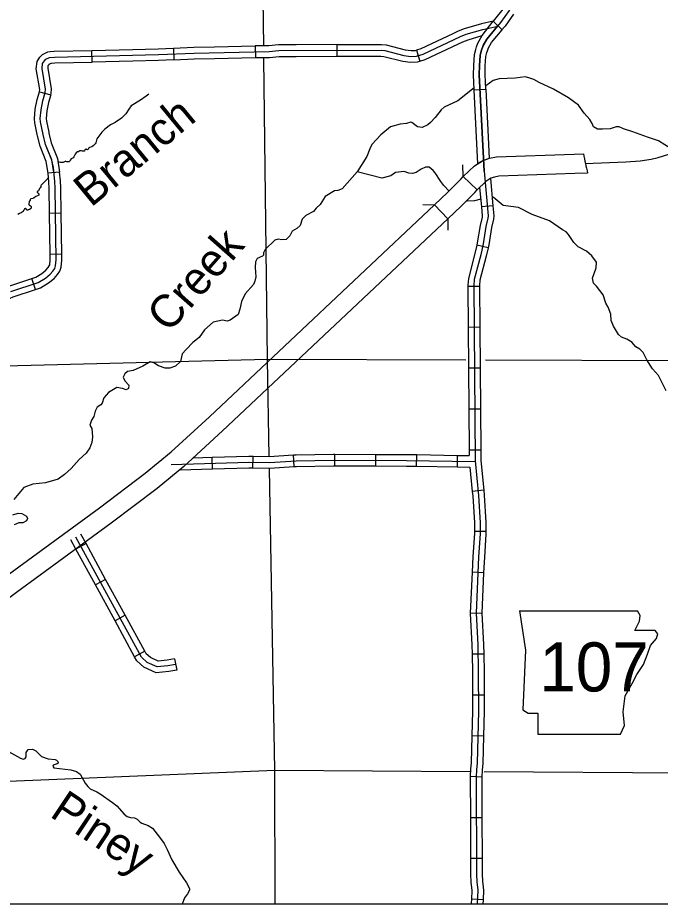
# Model space of a CAD drawing. Extents: x 1212896 to 1368412, y 378476 to 478763.
# Drawn here: x 1265961 to 1274256, y 388319 to 399763 of the extents above; entities that cross this region are included whole.
import ezdxf

# ---------------------------------------------------------------- set-up
doc = ezdxf.new("R2010")
doc.units = 0
for name, color, linetype in [('1', 7, 'Continuous'), ('Level 10', 7, 'Continuous'), ('Level 21', 7, 'Continuous'), ('Level 31', 7, 'Continuous'), ('Level 32', 7, 'Continuous'), ('Level 35', 7, 'Continuous'), ('Level 37', 7, 'Continuous'), ('Level 5', 7, 'Continuous'), ('Level 60', 7, 'Continuous')]:
    doc.layers.add(name, color=color, linetype=linetype)

msp = doc.modelspace()

# ---------------------------------------------------------------- linework, layer by layer
at = {"layer": '1'}
msp.add_lwpolyline([(1257400, 437504), (1319317, 437504), (1319317, 388319), (1257400, 388319)], close=True, dxfattribs=at)
at = {"layer": 'Level 10'}
for p, q in [((1271893, 397542), (1271710, 397712)), ((1271342, 397349), (1271515, 397169))]:
    msp.add_line(p, q, dxfattribs=at)
for points in [[(1273285, 397881), (1273811, 397904), (1273995, 397914), (1274137, 397939), (1274230, 397960), (1274366, 398002), (1274402, 398020), (1274547, 398112), (1275239, 398349)], [(1271710, 397712), (1271856, 397852), (1271961, 397917), (1272051, 397948), (1272143, 397966), (1273145, 398000), (1273262, 398005)], [(1271342, 397349), (1271511, 397509), (1271682, 397681), (1271710, 397712)], [(1273317, 397758), (1273154, 397751), (1272172, 397717), (1272116, 397706), (1272069, 397690), (1272004, 397650), (1271893, 397542)], [(1271515, 397169), (1271685, 397330), (1271863, 397509), (1271893, 397542)], [(1264197, 391366), (1264233, 391409), (1264355, 391513), (1265223, 392114), (1265798, 392545), (1267017, 393438), (1267605, 393882), (1267944, 394160), (1268436, 394612), (1271342, 397349)], [(1271515, 397169), (1268606, 394429), (1268107, 393971), (1267759, 393686), (1267166, 393238), (1265947, 392344), (1265369, 391912), (1264508, 391315), (1264410, 391231), (1264386, 391203)]]:
    msp.add_lwpolyline(points, dxfattribs=at)
msp.add_arc((1280772, 399533), 7663, 191.4984, 193.3964, dxfattribs=at)
at = {"layer": 'Level 21'}
for p, q in [((1272439, 392107), (1272516, 391600)), ((1273996, 392048), (1273961, 392107)), ((1273928, 391854), (1273987, 391972)), ((1273987, 391972), (1273996, 392048)), ((1274190, 391854), (1273928, 391854)), ((1274224, 391811), (1274190, 391854)), ((1274131, 391659), (1274207, 391752)), ((1274207, 391752), (1274224, 391811)), ((1272516, 391600), (1272482, 390830)), ((1274089, 391549), (1274131, 391659)), ((1274038, 391414), (1274089, 391549)), ((1273954, 391287), (1274038, 391414)), ((1273894, 391168), (1273954, 391287)), ((1273801, 391008), (1273894, 391168)), ((1273776, 390805), (1273801, 391008)), ((1272482, 390830), (1272549, 390788)), ((1273793, 390627), (1273776, 390805)), ((1272549, 390788), (1272676, 390788)), ((1272676, 390788), (1272676, 390517)), ((1273742, 390517), (1273793, 390627)), ((1272676, 390517), (1273742, 390517))]:
    msp.add_line(p, q, dxfattribs=at)
msp.add_lwpolyline([(1272439, 392107), (1273961, 392107)], dxfattribs=at)
at = {"layer": 'Level 31'}
for p, q in [((1269028, 399398), (1269031, 399248)), ((1270085, 399266), (1270085, 399416)), ((1266920, 399191), (1266917, 399341)), ((1267971, 399370), (1267977, 399220)), ((1271109, 399345), (1271153, 399202)), ((1271854, 398833), (1272004, 398841)), ((1266242, 398808), (1266387, 398768)), ((1266502, 397771), (1266353, 397756))]:
    msp.add_line(p, q, dxfattribs=at)
for points in [[(1266428, 397764), (1266400, 397927), (1266321, 398126), (1266290, 398256), (1266257, 398418), (1266252, 398460), (1266262, 398573), (1266287, 398688), (1266317, 398797), (1266320, 398840), (1266276, 399107), (1266282, 399171), (1266307, 399208), (1266324, 399226), (1266370, 399248), (1266436, 399255), (1267777, 399287), (1268237, 399306), (1269209, 399326), (1269330, 399338), (1270652, 399343), (1270702, 399338), (1270946, 399276), (1271037, 399263), (1271109, 399267), (1271194, 399293), (1271676, 399519), (1271749, 399550), (1271965, 399613), (1272160, 399656)], [(1272099, 399719), (1271947, 399686), (1271724, 399621), (1271645, 399588), (1271580, 399557)], [(1271981, 397782), (1271920, 399027), (1271922, 399145), (1271932, 399276), (1271945, 399333), (1271970, 399405), (1272016, 399484), (1272156, 399655)], [(1271958, 399533), (1272099, 399719)], [(1272099, 399719), (1272214, 399607)], [(1271580, 399557), (1271167, 399363), (1271109, 399345)], [(1271644, 399422), (1271706, 399451), (1271774, 399479), (1271958, 399533)], [(1271884, 399386), (1271902, 399436), (1271958, 399533)], [(1272026, 399336), (1272039, 399373), (1272078, 399441), (1272214, 399607)], [(1267971, 399370), (1268235, 399381), (1268500, 399387)], [(1268500, 399387), (1269028, 399398)], [(1269557, 399414), (1269326, 399413), (1269204, 399401), (1269028, 399398)], [(1270085, 399416), (1269557, 399414)], [(1270085, 399416), (1270613, 399418)], [(1270613, 399418), (1270656, 399418), (1270716, 399412), (1270961, 399350), (1271040, 399339), (1271096, 399341), (1271109, 399345)], [(1271153, 399202), (1271221, 399222), (1271644, 399422)], [(1271854, 398833), (1271845, 399026), (1271847, 399148), (1271857, 399287), (1271873, 399354), (1271884, 399386)], [(1266242, 398808), (1266243, 398811), (1266245, 398837), (1266201, 399105), (1266210, 399196), (1266248, 399255), (1266280, 399288), (1266350, 399321), (1266382, 399325)], [(1266382, 399325), (1266430, 399330), (1266917, 399341)], [(1266917, 399341), (1267445, 399354)], [(1267445, 399354), (1267775, 399362), (1267971, 399370)], [(1270085, 399266), (1270613, 399268)], [(1270613, 399268), (1270648, 399268), (1270689, 399264), (1270932, 399202), (1271033, 399188), (1271122, 399192), (1271153, 399202)], [(1272004, 398841), (1271995, 399028), (1271997, 399141), (1272006, 399264), (1272017, 399312), (1272026, 399336)], [(1266387, 398768), (1266391, 398784), (1266396, 398844), (1266352, 399110), (1266355, 399145), (1266365, 399160), (1266368, 399164), (1266391, 399175), (1266399, 399176)], [(1266399, 399176), (1266441, 399180), (1266920, 399191)], [(1267448, 399204), (1266920, 399191)], [(1267977, 399220), (1267780, 399212), (1267448, 399204)], [(1267977, 399220), (1268240, 399231), (1268503, 399237)], [(1268503, 399237), (1269031, 399248)], [(1269031, 399248), (1269213, 399251), (1269334, 399263), (1269557, 399264)], [(1269557, 399264), (1270085, 399266)], [(1271880, 398306), (1271854, 398833)], [(1272004, 398841), (1272030, 398313)], [(1266214, 398255), (1266183, 398406), (1266177, 398459), (1266188, 398584), (1266214, 398706), (1266242, 398808)], [(1266387, 398768), (1266360, 398670), (1266336, 398562), (1266328, 398460), (1266331, 398429), (1266361, 398286)], [(1266353, 397756), (1266327, 397907), (1266250, 398104), (1266217, 398240), (1266214, 398255)], [(1266361, 398286), (1266363, 398273), (1266393, 398149), (1266473, 397947), (1266502, 397771)], [(1271901, 397880), (1271880, 398306)], [(1272030, 398313), (1272048, 397947)], [(1272048, 397947), (1271961, 397917), (1271901, 397880)]]:
    msp.add_lwpolyline(points, dxfattribs=at)
at = {"layer": 'Level 32'}
for p, q in [((1272096, 397336), (1271947, 397322)), ((1266523, 397238), (1266373, 397236)), ((1272034, 396793), (1271887, 396825)), ((1266529, 396710), (1266379, 396708)), ((1266192, 396255), (1266145, 396398)), ((1271923, 396295), (1271773, 396294)), ((1271927, 395767), (1271777, 395766)), ((1271931, 395239), (1271781, 395238)), ((1271935, 394711), (1271785, 394710)), ((1269531, 393970), (1269522, 394119)), ((1270054, 393980), (1270055, 394130)), ((1270582, 393977), (1270583, 394127)), ((1271109, 393973), (1271112, 394123)), ((1271939, 394183), (1271789, 394182)), ((1268474, 393941), (1268469, 394090)), ((1268998, 393954), (1269001, 394104)), ((1271637, 393964), (1271640, 394114)), ((1271978, 393663), (1271829, 393649)), ((1272006, 393129), (1271856, 393129)), ((1266843, 392976), (1266711, 392904)), ((1271975, 392599), (1271826, 392606)), ((1267096, 392513), (1266964, 392441)), ((1271951, 392079), (1271801, 392071)), ((1267349, 392049), (1267217, 391978)), ((1267602, 391586), (1267470, 391514)), ((1267983, 391489), (1268013, 391342)), ((1271976, 391549), (1271826, 391546)), ((1271982, 391020), (1271832, 391019)), ((1271975, 390490), (1271825, 390493)), ((1271953, 389962), (1271803, 389967)), ((1271954, 389437), (1271804, 389436)), ((1271956, 388909), (1271806, 388908)), ((1271968, 388378), (1271818, 388385))]:
    msp.add_line(p, q, dxfattribs=at)
for points in [[(1272636, 400916), (1272539, 400477), (1272461, 400213), (1272421, 400100), (1272345, 399927), (1272306, 399857), (1272194, 399700), (1272016, 399484), (1271970, 399405), (1271945, 399333), (1271932, 399276), (1271922, 399145), (1271920, 399027), (1271981, 397782)], [(1272239, 399894), (1272099, 399719)], [(1272360, 399807), (1272252, 399655), (1272203, 399596)], [(1265874, 396228), (1266226, 396344), (1266318, 396399), (1266379, 396451), (1266416, 396492), (1266438, 396525), (1266450, 396559), (1266456, 396636), (1266445, 397562), (1266440, 397651), (1266422, 397830), (1266400, 397926), (1266321, 398126), (1266290, 398256), (1266257, 398418), (1266252, 398460), (1266262, 398573), (1266287, 398688), (1266317, 398797), (1266320, 398840), (1266276, 399107), (1266282, 399171), (1266307, 399208), (1266324, 399226), (1266370, 399248), (1266436, 399255), (1267777, 399287), (1268237, 399306), (1269209, 399326), (1269330, 399338), (1270652, 399343), (1270702, 399338), (1270946, 399276), (1271037, 399263), (1271109, 399267), (1271194, 399293), (1271676, 399519), (1271749, 399550), (1271965, 399613), (1272160, 399656)], [(1271981, 397782), (1272034, 397207), (1272031, 397176), (1272006, 397068), (1271969, 396844), (1271938, 396703), (1271855, 396386), (1271849, 396307), (1271867, 394042), (1271911, 393596), (1271932, 393243), (1271932, 393101), (1271911, 392803), (1271878, 392077), (1271899, 391670), (1271907, 391314), (1271909, 390813), (1271893, 390141), (1271882, 390061), (1271879, 389956), (1271883, 388708), (1271887, 388611), (1271900, 388500), (1271892, 388325), (1271891, 388319)], [(1266373, 397236), (1266369, 397559), (1266364, 397645), (1266353, 397756)], [(1266523, 397238), (1266519, 397565), (1266514, 397656), (1266502, 397771)], [(1272063, 397688), (1272096, 397336)], [(1271924, 397571), (1271947, 397322)], [(1271947, 397322), (1271957, 397207), (1271955, 397188), (1271931, 397083), (1271894, 396858), (1271887, 396825)], [(1272096, 397336), (1272108, 397207), (1272104, 397164), (1272078, 397054), (1272042, 396830), (1272034, 396793)], [(1266379, 396708), (1266373, 397236)], [(1266529, 396710), (1266523, 397238)], [(1271887, 396825), (1271864, 396721), (1271779, 396398), (1271773, 396310), (1271773, 396294)], [(1272034, 396793), (1272010, 396686), (1271928, 396374), (1271923, 396305), (1271923, 396295)], [(1266145, 396398), (1266194, 396414), (1266273, 396462), (1266326, 396506), (1266355, 396538), (1266369, 396559), (1266374, 396575), (1266380, 396639), (1266379, 396708)], [(1266192, 396255), (1266257, 396277), (1266360, 396339), (1266431, 396398), (1266475, 396447), (1266505, 396492), (1266522, 396543), (1266530, 396633), (1266529, 396710)], [(1265645, 396210), (1265847, 396299), (1266145, 396398)], [(1271773, 396294), (1271777, 395766)], [(1271923, 396295), (1271927, 395767)], [(1265705, 396073), (1265901, 396159), (1266192, 396255)], [(1271777, 395766), (1271781, 395238)], [(1271927, 395767), (1271931, 395239)], [(1271781, 395238), (1271785, 394710)], [(1271931, 395239), (1271935, 394711)], [(1271785, 394710), (1271789, 394182)], [(1271935, 394711), (1271939, 394183)], [(1269001, 394104), (1269209, 394100), (1269522, 394119)], [(1269522, 394119), (1269554, 394121), (1270038, 394130), (1270055, 394130)], [(1270055, 394130), (1270583, 394127)], [(1270583, 394127), (1270979, 394126), (1271112, 394123)], [(1271112, 394123), (1271640, 394114)], [(1271789, 394182), (1271790, 394112)], [(1271939, 394183), (1271940, 394046), (1271978, 393663)], [(1267944, 393998), (1268945, 394028), (1269211, 394023), (1269557, 394045), (1270039, 394053), (1270978, 394049), (1271867, 394034)], [(1268230, 394083), (1268469, 394090)], [(1268469, 394090), (1268944, 394105), (1269001, 394104)], [(1271640, 394114), (1271790, 394112)], [(1268055, 393928), (1268474, 393941)], [(1268474, 393941), (1268945, 393955), (1268998, 393954)], [(1268998, 393954), (1269212, 393950), (1269531, 393970)], [(1269531, 393970), (1269560, 393971), (1270039, 393980), (1270054, 393980)], [(1270054, 393980), (1270582, 393977)], [(1270582, 393977), (1270978, 393976), (1271109, 393973)], [(1271109, 393973), (1271637, 393964)], [(1271637, 393964), (1271798, 393962)], [(1271798, 393962), (1271829, 393649)], [(1271978, 393663), (1271984, 393602), (1272006, 393246), (1272006, 393129)], [(1271829, 393649), (1271834, 393590), (1271856, 393241), (1271856, 393129)], [(1266843, 392976), (1266777, 393096)], [(1271856, 393129), (1271856, 393104), (1271835, 392807), (1271826, 392606)], [(1272006, 393129), (1272006, 393098), (1271985, 392798), (1271975, 392599)], [(1266711, 392904), (1266646, 393024)], [(1267998, 391415), (1267900, 391396), (1267762, 391383), (1267631, 391442), (1267559, 391507), (1266712, 393060)], [(1267096, 392513), (1266843, 392976)], [(1266964, 392441), (1266711, 392904)], [(1271826, 392606), (1271801, 392077), (1271801, 392071)], [(1271975, 392599), (1271951, 392078)], [(1267217, 391978), (1266964, 392441)], [(1267349, 392049), (1267096, 392513)], [(1271801, 392071), (1271823, 391668), (1271826, 391546)], [(1271951, 392079), (1271973, 391673), (1271976, 391549)], [(1267470, 391514), (1267217, 391978)], [(1267602, 391586), (1267349, 392049)], [(1268013, 391342), (1267911, 391322), (1267750, 391306), (1267590, 391378), (1267500, 391460), (1267470, 391514)], [(1267983, 391489), (1267889, 391470), (1267775, 391459), (1267673, 391505), (1267619, 391554), (1267602, 391586)], [(1271826, 391546), (1271831, 391313), (1271832, 391019)], [(1271976, 391549), (1271981, 391315), (1271982, 391020)], [(1271832, 391019), (1271833, 390814), (1271825, 390493)], [(1271982, 391020), (1271983, 390813), (1271975, 390490)], [(1271825, 390493), (1271816, 390146), (1271806, 390067), (1271803, 389967)], [(1271975, 390490), (1271966, 390135), (1271956, 390055), (1271953, 389962)], [(1271803, 389967), (1271802, 389957), (1271804, 389436)], [(1271953, 389962), (1271952, 389955), (1271954, 389437)], [(1271804, 389436), (1271806, 388908)], [(1271954, 389437), (1271956, 388909)], [(1271806, 388908), (1271807, 388706), (1271811, 388605), (1271823, 388497), (1271818, 388385)], [(1271956, 388909), (1271957, 388709), (1271960, 388616), (1271973, 388503), (1271968, 388378)], [(1271818, 388385), (1271815, 388332), (1271814, 388319)], [(1271968, 388378), (1271965, 388319)]]:
    msp.add_lwpolyline(points, dxfattribs=at)
at = {"layer": 'Level 35'}
for points in [[(1274397, 398070), (1274235, 398173), (1274091, 398220), (1273903, 398291), (1273779, 398327), (1273726, 398355), (1273685, 398354), (1273608, 398330), (1273509, 398324), (1273447, 398326), (1273395, 398353), (1273378, 398397), (1273345, 398450), (1273273, 398529), (1273201, 398635), (1273071, 398727), (1272876, 398841), (1272693, 398925), (1272624, 398964), (1272559, 398989), (1272513, 399000), (1272384, 398983), (1272175, 398974), (1272099, 398953), (1272050, 398918), (1272002, 398884)], [(1271852, 398860), (1271644, 398692), (1271467, 398610), (1271429, 398575), (1271348, 398474), (1271288, 398409), (1271254, 398381), (1271183, 398346), (1271122, 398354), (1271048, 398411), (1271035, 398414), (1270981, 398398), (1270898, 398387), (1270773, 398354), (1270649, 398251), (1270532, 398126), (1270505, 398069), (1270468, 397971), (1270343, 397774), (1270149, 397553), (1270092, 397532), (1270052, 397528), (1269928, 397456), (1269866, 397351), (1269815, 397306), (1269778, 397260), (1269680, 397212), (1269632, 397163), (1269607, 397079), (1269563, 397041), (1269505, 397008), (1269472, 396946), (1269426, 396899)], [(1267654, 398778), (1267621, 398750), (1267546, 398698), (1267427, 398627), (1267394, 398584), (1267356, 398524), (1267300, 398468), (1267218, 398410), (1267158, 398379), (1267084, 398323), (1267046, 398287), (1266983, 398201)], [(1266983, 398201), (1266970, 398150), (1266961, 398137), (1266951, 398126), (1266933, 398110), (1266918, 398097), (1266887, 398088), (1266879, 398082), (1266875, 398076), (1266872, 398064), (1266868, 398061), (1266861, 398059), (1266852, 398064), (1266848, 398065), (1266844, 398065), (1266839, 398064), (1266832, 398061), (1266827, 398057), (1266822, 398042), (1266816, 398040), (1266806, 398040), (1266796, 398040), (1266784, 398045), (1266774, 398046), (1266763, 398045), (1266749, 398035)], [(1266748, 398035), (1266746, 398033), (1266734, 398031), (1266715, 398019), (1266703, 398000), (1266694, 397984), (1266684, 397966), (1266678, 397955), (1266670, 397950), (1266649, 397940), (1266639, 397926), (1266628, 397906), (1266623, 397903), (1266618, 397902), (1266606, 397902), (1266594, 397904), (1266584, 397909), (1266580, 397910), (1266575, 397909), (1266558, 397897), (1266547, 397894), (1266534, 397892), (1266524, 397892), (1266515, 397892), (1266496, 397900), (1266488, 397899), (1266483, 397894), (1266482, 397892)], [(1271529, 397524), (1271463, 397596), (1271422, 397647), (1271349, 397759), (1271324, 397790), (1271271, 397833), (1271225, 397832), (1271169, 397808), (1271104, 397765), (1271056, 397753), (1271012, 397757), (1270949, 397777), (1270837, 397766), (1270776, 397721), (1270662, 397694), (1270343, 397774)], [(1266358, 397705), (1266339, 397678), (1266315, 397652), (1266284, 397623), (1266265, 397602), (1266261, 397592), (1266258, 397578), (1266251, 397566), (1266243, 397558), (1266237, 397548), (1266230, 397530), (1266218, 397521), (1266214, 397516), (1266213, 397511), (1266215, 397507), (1266218, 397503), (1266227, 397497), (1266233, 397490), (1266235, 397483), (1266235, 397477), (1266232, 397471), (1266218, 397464), (1266194, 397454), (1266172, 397439), (1266162, 397432), (1266155, 397429), (1266136, 397426), (1266131, 397424), (1266127, 397422), (1266123, 397416), (1266120, 397407), (1266110, 397389), (1266107, 397377), (1266105, 397368), (1266105, 397352), (1266109, 397346), (1266127, 397333), (1266133, 397325), (1266135, 397316), (1266134, 397306)], [(1274331, 394946), (1274232, 395145), (1274156, 395232), (1274081, 395348), (1274033, 395443), (1273991, 395485), (1273940, 395516), (1273888, 395573), (1273824, 395613), (1273757, 395640), (1273717, 395676), (1273653, 395783), (1273624, 395853), (1273616, 395937), (1273584, 396027), (1273552, 396079), (1273520, 396184), (1273434, 396296), (1273394, 396335), (1273380, 396401), (1273429, 396536), (1273433, 396607), (1273373, 396691), (1273305, 396749), (1273197, 396805), (1273138, 396860), (1273072, 396966), (1273040, 397001), (1272995, 397027), (1272826, 397143), (1272603, 397223), (1272427, 397315), (1272227, 397337), (1272099, 397447)], [(1271940, 397419), (1271858, 397398), (1271762, 397393), (1271755, 397395)], [(1266134, 397306), (1266125, 397297), (1266113, 397289), (1266101, 397285), (1266094, 397282), (1266087, 397279), (1266081, 397281), (1266075, 397285), (1266068, 397295), (1266064, 397298), (1266060, 397300), (1266055, 397299), (1266050, 397296), (1266039, 397280), (1266027, 397261), (1266017, 397252), (1266006, 397245), (1265985, 397237), (1265961, 397221)], [(1269426, 396899), (1269369, 396895), (1269323, 396905), (1269278, 396893), (1269157, 396772), (1269133, 396727), (1269132, 396699), (1269122, 396687), (1269053, 396656), (1269032, 396613), (1269025, 396539), (1269033, 396420), (1269022, 396363), (1269003, 396320), (1268895, 396198), (1268848, 396102), (1268828, 396002), (1268807, 395932), (1268704, 395860), (1268663, 395848), (1268605, 395859), (1268485, 395831), (1268371, 395736), (1268304, 395637), (1268221, 395569), (1268134, 395482), (1268085, 395423), (1268063, 395327), (1267998, 395266), (1267924, 395238), (1267863, 395241), (1267778, 395271), (1267717, 395310), (1267672, 395319), (1267575, 395266), (1267453, 395211), (1267380, 395198), (1267342, 395168), (1267322, 395124), (1267345, 395078), (1267397, 395022), (1267390, 394978), (1267359, 394961), (1267315, 394977), (1267240, 394989), (1267133, 394926), (1267071, 394857), (1267050, 394788), (1267032, 394768), (1266986, 394734), (1266961, 394685), (1266945, 394614), (1266913, 394566), (1266894, 394505), (1266917, 394460), (1266928, 394352), (1266918, 394279), (1266894, 394213), (1266845, 394142), (1266756, 394062), (1266653, 393946), (1266567, 393866), (1266481, 393808), (1266318, 393760), (1266156, 393742), (1266039, 393698), (1265909, 393542)], [(1265899, 393348), (1265965, 393367), (1266014, 393365), (1266075, 393331), (1266086, 393300), (1266073, 393267), (1266029, 393242), (1265977, 393241), (1265916, 393219)], [(1265805, 390311), (1265998, 390204), (1266031, 390193), (1266055, 390199), (1266068, 390223), (1266068, 390279), (1266098, 390318), (1266152, 390323), (1266196, 390298), (1266269, 390226), (1266355, 390198), (1266446, 390190), (1266462, 390181), (1266478, 390163), (1266481, 390141), (1266469, 390132), (1266419, 390113), (1266415, 390100), (1266426, 390079), (1266648, 390053), (1266719, 390033), (1266765, 389999), (1266832, 389884), (1266868, 389838), (1266896, 389811), (1266983, 389772), (1267026, 389746), (1267183, 389632), (1267241, 389588), (1267337, 389482), (1267373, 389451), (1267418, 389439), (1267468, 389436), (1267505, 389419), (1267542, 389381), (1267565, 389365), (1267644, 389337), (1267701, 389303), (1267790, 389185)], [(1267790, 389185), (1267850, 389103), (1267890, 389027), (1267949, 388892), (1268044, 388732), (1268141, 388598), (1268180, 388523), (1268179, 388500), (1268153, 388454), (1268115, 388401), (1268085, 388319)]]:
    msp.add_lwpolyline(points, dxfattribs=at)
at = {"layer": 'Level 37'}
for points in [[(1271710, 397712), (1271705, 397862)], [(1271192, 397352), (1271342, 397349)], [(1271515, 397169), (1271512, 397019)]]:
    msp.add_lwpolyline(points, dxfattribs=at)
at = {"layer": 'Level 5'}
for points in [[(1269138, 399396), (1269123, 400619)], [(1269207, 394094), (1269185, 395352), (1269139, 399237)], [(1271746, 395343), (1269185, 395352), (1264944, 395243)], [(1274483, 395333), (1272000, 395342)], [(1269284, 388319), (1269278, 390049), (1269210, 393940)], [(1264377, 389849), (1269278, 390049), (1271801, 390034)], [(1271983, 390032), (1274535, 390017)]]:
    msp.add_lwpolyline(points, dxfattribs=at)
at = {"layer": 'Level 60'}
msp.add_spline([(1275538, 388463), (1274493, 424373), (1274106, 437641)], degree=3, dxfattribs=at)

# ---------------------------------------------------------------- texts
at = {"layer": 'Level 21'}
msp.add_text('107', height=633.6, dxfattribs=at).set_placement((1272694, 391066))
at = {"layer": 'Level 35'}
for s, rotation, p in [('Branch', 39.4867, (1266906, 397307)), ('Creek', 48.6341, (1267911, 395682)), ('Piney', 326.3118, (1266360, 389460))]:
    msp.add_text(s, height=422.4, rotation=rotation, dxfattribs=at).set_placement(p)

doc.saveas('drawing.dxf')
